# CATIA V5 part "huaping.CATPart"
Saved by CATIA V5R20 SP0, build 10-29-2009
Part number: 花瓶
Bounding box of the stored display mesh (mm): x -19.999 to 19.999, y -19.999 to 19.978, z -1 to 80.298
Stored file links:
  D:\3D工程制图\huaping.CATPart
  D:\CATIAR20\win_b64\startup\materials\Catalog.CATMaterial
  D:\CATIAR20\win_b64\startup\materials\wall_of_bricks.jpg
  D:\CATIAR20\win_b64\startup\materials\canvas.png
  D:\CATIAR20\win_b64\startup\materials\blue_fabric_02.jpg
  D:\CATIAR20\win_b64\startup\materials\chessboard.jpg
  D:\CATIAR20\win_b64\startup\materials\marble.jpg
  D:\CATIAR20\win_b64\startup\materials\brushed_metal1.jpg
  D:\CATIAR20\win_b64\startup\materials\raw_polystyren.jpg
  D:\CATIAR20\win_b64\startup\materials\DS_star.jpg
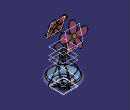
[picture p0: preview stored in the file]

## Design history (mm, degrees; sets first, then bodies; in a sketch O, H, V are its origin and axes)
Body1 (main body)
  Sketch1 on xy-plane, origin (0, 0, 0), H (1, 0, 0), V (0, 1, 0)
    circle A1 centre (0, 0) radius 5
    radius A1 = 5
  Plane1: type Offset, RefPlane xy-plane, Offset 10
  Sketch2 on Plane1, origin (0, 0, 10), H (1, 0, 0), V (0, 1, 0)
    circle A1 centre (0, 0) radius 20
    radius A1 = 20
  Plane2: type Offset, RefPlane Plane1, Offset 20
  Sketch3 on Plane2, origin (0, 0, 30), H (1, 0, 0), V (0, 1, 0)
    circle A1 centre (0, 0) radius 6.75
    radius A1 = 6.75
  Plane3: type Offset, RefPlane Plane2, Offset 5
  Sketch4 on Plane3, origin (0, 0, 35), H (1, 0, 0), V (0, 1, 0)
    circle A1 centre (0, 0) radius 5
    radius A1 = 5
  Plane4: type Offset, RefPlane Plane3, Offset 10
  Sketch5 on Plane4, origin (0, 0, 45), H (1, 0, 0), V (0, 1, 0)
    circle A1 centre (0, 0) radius 9
    radius A1 = 9
  Plane5: type Offset, RefPlane xy-plane, Offset 1, reversed
  Sketch6 on Plane5, origin (0, 0, -1), H (1, 0, 0), V (0, 1, 0)
    circle A1 centre (0, 0) radius 5.5
    radius A1 = 5.5
  Loft1: solid, Sections (Sketch6; Sketch1; Sketch2; Sketch3; Sketch4; Sketch5)
  Shell1: IntOffset 0.5, Face face of Loft1, ExtOffset 0
  Fillet1: radius 0.2, on edge [face of Loft1 | face of Loft1]; edge [face of Loft1 | face of Shell1]
Body2
  Sketch7 on yz-plane, origin (0, 0, 0), H (0, 1, 0), V (0, 0, 1)
    spline S1 through (1.8636, 1.4943) (5.887, 18.6974) (-1.8048, 31.1548) (-1.0948, 41.7139) (0.9169, 52.8663) (-10.2067, 62.8322)
  Plane6: type Normal, Curve Sketch7, RefPoint vertex of Sketch7
  Circle1: type CtrRad, Start 0, End 180, Radius 0.5, Center vertex of Sketch7, Support Plane6, FirstDirection (1, 0, 0)
  Rib1: profile Circle1, centre curve Sketch7
  Sketch8 on Plane6, origin (0, -26.5611, 7.9091), H (1, 0, 0), V (0, 0.2854, 0.9584)
    spline S1 through (0.3814, 52.4257) (8.1821, 46.8741) (10.4301, 53.172) (3.917, 57.0899) (9.6858, 60.6347) (7.3212, 67.6168) (0.6221, 65.3779) (-0.6805, 61.0869) (-2.699, 65.5337) (-9.9849, 68.1765) (-11.8458, 59.5943) (-5.4903, 56.765) (-10.7008, 54.3396) (-10.9269, 49.3566) (-6.4608, 45.2521) (-1.9947, 46.7447) (0.3814, 52.4257)
    point P1 (0.3814, 52.4257)
    point P2 (0.3814, 52.4257)
    coincidence: P1 P2
  Pad1: profile Sketch8, direction (0, -0.9584, 0.2854), length 1
  Sketch9 on end face of Pad1, origin (0, -27.5195, 8.1944), H (1, 0, 0), V (0, 0.2854, 0.9584)
    circle A1 centre (-0.6599, 56.4821) radius 4
    radius A1 = 4
  Pad2: profile Sketch9, direction (0, -0.9584, 0.2854), length 0.5
Body3
  Sketch10 on yz-plane, origin (0, 0, 0), H (0, 1, 0), V (0, 0, 1)
    spline S1 through (-1.1144, 1.9459) (-5.0146, 18.9833) (0, 32.669) (2.925, 48.0306) (6.4073, 58.9233) (14.2075, 63.9508)
    point P1 (0, 32.669)
    coincidence: P1 V
  Plane7: type Normal, Curve Sketch10, RefPoint vertex of Sketch10
  Circle2: type CtrRad, Start 0, End 180, Radius 0.4, Center vertex of Sketch10, Support Plane7, FirstDirection (1, 0, 0)
  Rib2: profile Circle2, centre curve Sketch10
  Sketch11 on Plane7, origin (0, 28.8356, 7.4679), H (1, 0, 0), V (0, -0.2507, 0.9681)
    spline S1 through (-3.9843, 61.2707) (-6.0652, 69.0367) (-2.5928, 74.9404) (3.7538, 69.7399) (3.2958, 62.0471) (5.8578, 64.2552) (18.2129, 62.9138) (12.4505, 56.3797) (4.0343, 57.3642) (10.8319, 52.353) (11.3929, 45.8839) (3.4732, 48.5043) (0.6626, 54.7482) (-1.2115, 47.9425) (-6.9396, 43.508) (-7.5575, 50.3325) (-4.1392, 55.68) (-11.0643, 53.5671) (-18.4986, 60.1768) (-10.3629, 62.9895) (-3.9843, 61.2707)
    point P1 (-3.9843, 61.2707)
    point P2 (-3.9843, 61.2707)
    coincidence: P1 P2
  Pad3: profile Sketch11, direction (0, -0.9681, -0.2507), length 0.5
  Sketch12 on face of Pad3, origin (0, 28.8356, 7.4679), H (-1, 0, 0), V (0, -0.2507, 0.9681)
    circle A1 centre (0.166, 58.725) radius 3
    radius A1 = 3
  Pad4: profile Sketch12, direction (0, 0.9681, 0.2507), length 0.2
Body4
  Sketch13 on yz-plane, origin (0, 0, 0), H (0, 1, 0), V (0, 0, 1)
    axis line L1 (0, 62.8473) -> (0, -13.7323)
    point P1 (0, 62.8473)
    point P3 (0, 13.4258)
    line L2 (0, 13.4258) -> (16.3548, 13.4258)
    arc A1 centre (16.3548, 12.1645) radius 1.2613 from (16.3548, 13.4258) to (17.6161, 12.1645) cw
    arc A2 centre (11.0706, 12.1645) radius 6.5456 from (17.6161, 12.1645) to (11.0706, 5.6189) cw
    arc A3 centre (11.0706, -5.4516) radius 11.0706 from (11.0706, 5.6189) to (7.2111, 4.9244) ccw
    line L3 (7.2111, 4.9244) -> (4.3949, 3.8769)
    line L4 (4.3949, 3.8769) -> (2.4947, 1.5492)
    point P12 (2.4947, 1.5492)
    line L5 (2.4947, 1.5492) -> (2.0622, 1.0194)
    line L6 (2.0622, 1.0194) -> (0, 1.0194)
    point P14 (0, 1.0194)
    coincidence: P1 V, P3 L1, P12 A3, P14 L1
    vertical: L1 V
    horizontal: L2 H, L6 H
    tangency: A1 L2, A2 A1, A3 L1, A3 A2, L3 A3, L4 A3, L5 A3
  Shaft1: profile Sketch13, axis Sketch13.L1, angle 360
